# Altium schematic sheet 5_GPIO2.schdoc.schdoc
size 426 x 302 mm; Symbol: Sheet_A3_Whycan; Device: Sheet_A3; @Project Name: Avaota A1; REV: 1.0; Company: YuzukiHD; Draw By: GloomyGhost; @Update Date: 2024-02-28; @Page No: 7; @Page Count: 13
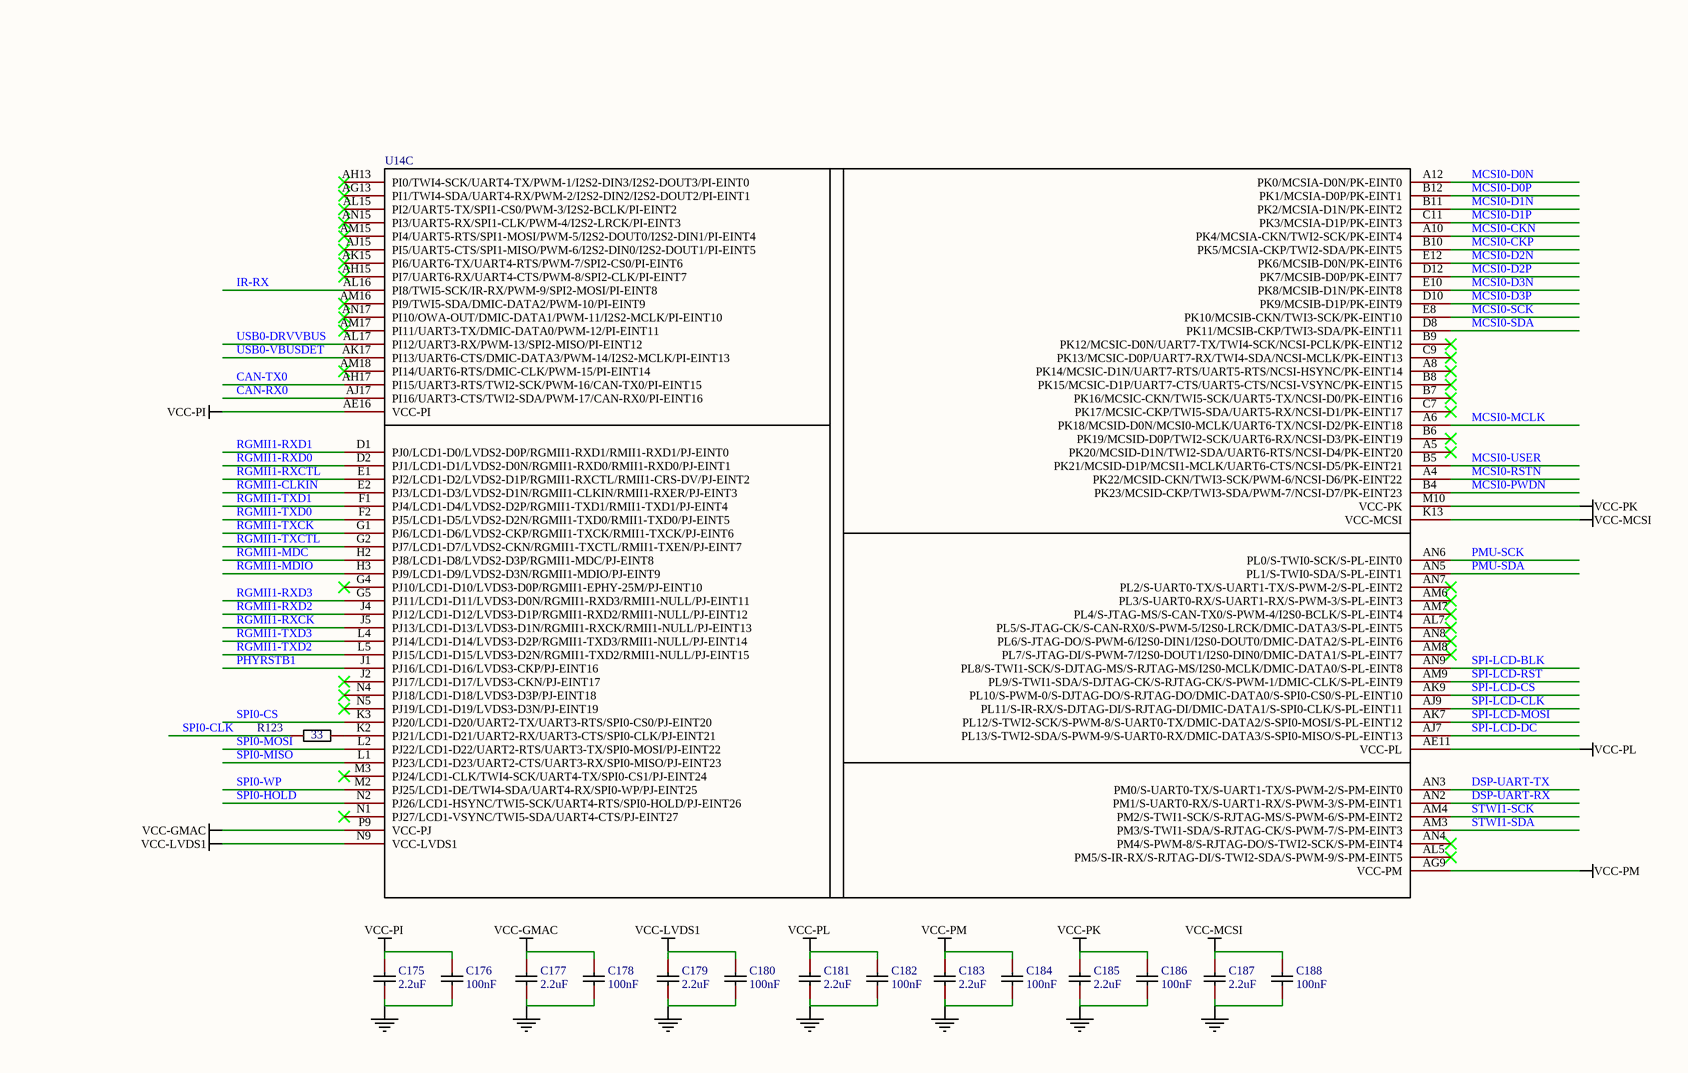
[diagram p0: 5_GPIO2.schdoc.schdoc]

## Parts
C175  2.2uF  [c0201 nsk]
C176  100nF  [c0201 nsk]
C177  2.2uF  [c0201 nsk]
C178  100nF  [c0201 nsk]
C179  2.2uF  [c0201 nsk]
C180  100nF  [c0201 nsk]
C181  2.2uF  [c0201 nsk]
C182  100nF  [c0201 nsk]
C183  2.2uF  [c0201 nsk]
C184  100nF  [c0201 nsk]
C185  2.2uF  [c0201 nsk]
C186  100nF  [c0201 nsk]
C187  2.2uF  [c0201 nsk]
C188  100nF  [c0201 nsk]
R123  33  [r0201 nsk]
U14  T527  [T527-BGA664]  (value not drawn)  (part C of 8)

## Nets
NetC175_1: C175.1 C176.1 C177.1 C178.1 C179.1 C180.1 C181.1 C182.1 C183.1 C184.1 C185.1 C186.1 C187.1 C188.1
VCC-GMAC: C177.2 C178.2 U14.P9(VCC-PJ)
VCC-LVDS1: C179.2 C180.2 U14.N9(VCC-LVDS1)
VCC-MCSI: C187.2 C188.2 U14.K13(VCC-MCSI)
VCC-PI: C175.2 C176.2 U14.AE16(VCC-PI)
VCC-PK: C185.2 C186.2 U14.M10(VCC-PK)
VCC-PL: C181.2 C182.2 U14.AE11(VCC-PL)
VCC-PM: C183.2 C184.2 U14.AG9(VCC-PM)
CAN-RX0: U14.AJ17(PI16/UART3-CTS/TWI2-SDA/PWM-17/CAN-RX0/PI-EINT16)
CAN-TX0: U14.AH17(PI15/UART3-RTS/TWI2-SCK/PWM-16/CAN-TX0/PI-EINT15)
DSP-UART-RX: U14.AN2(PM1/S-UART0-RX/S-UART1-RX/S-PWM-3/S-PM-EINT1)
DSP-UART-TX: U14.AN3(PM0/S-UART0-TX/S-UART1-TX/S-PWM-2/S-PM-EINT0)
IR-RX: U14.AL16(PI8/TWI5-SCK/IR-RX/PWM-9/SPI2-MOSI/PI-EINT8)
MCSI0-CKN: U14.A10(PK4/MCSIA-CKN/TWI2-SCK/PK-EINT4)
MCSI0-CKP: U14.B10(PK5/MCSIA-CKP/TWI2-SDA/PK-EINT5)
MCSI0-D0N: U14.A12(PK0/MCSIA-D0N/PK-EINT0)
MCSI0-D0P: U14.B12(PK1/MCSIA-D0P/PK-EINT1)
MCSI0-D1N: U14.B11(PK2/MCSIA-D1N/PK-EINT2)
MCSI0-D1P: U14.C11(PK3/MCSIA-D1P/PK-EINT3)
MCSI0-D2N: U14.E12(PK6/MCSIB-D0N/PK-EINT6)
MCSI0-D2P: U14.D12(PK7/MCSIB-D0P/PK-EINT7)
MCSI0-D3N: U14.E10(PK8/MCSIB-D1N/PK-EINT8)
MCSI0-D3P: U14.D10(PK9/MCSIB-D1P/PK-EINT9)
MCSI0-MCLK: U14.A6(PK18/MCSID-D0N/MCSI0-MCLK/UART6-TX/NCSI-D2/PK-EINT18)
MCSI0-PWDN: U14.B4(PK23/MCSID-CKP/TWI3-SDA/PWM-7/NCSI-D7/PK-EINT23)
MCSI0-RSTN: U14.A4(PK22/MCSID-CKN/TWI3-SCK/PWM-6/NCSI-D6/PK-EINT22)
MCSI0-SCK: U14.E8(PK10/MCSIB-CKN/TWI3-SCK/PK-EINT10)
MCSI0-SDA: U14.D8(PK11/MCSIB-CKP/TWI3-SDA/PK-EINT11)
MCSI0-USER: U14.B5(PK21/MCSID-D1P/MCSI1-MCLK/UART6-CTS/NCSI-D5/PK-EINT21)
PHYRSTB1: U14.J1(PJ16/LCD1-D16/LVDS3-CKP/PJ-EINT16)
PMU-SCK: U14.AN6(PL0/S-TWI0-SCK/S-PL-EINT0)
PMU-SDA: U14.AN5(PL1/S-TWI0-SDA/S-PL-EINT1)
RGMII1-CLKIN: U14.E2(PJ3/LCD1-D3/LVDS2-D1N/RGMII1-CLKIN/RMII1-RXER/PJ-EINT3)
RGMII1-MDC: U14.H2(PJ8/LCD1-D8/LVDS2-D3P/RGMII1-MDC/PJ-EINT8)
RGMII1-MDIO: U14.H3(PJ9/LCD1-D9/LVDS2-D3N/RGMII1-MDIO/PJ-EINT9)
RGMII1-RXCK: U14.J5(PJ13/LCD1-D13/LVDS3-D1N/RGMII1-RXCK/RMII1-NULL/PJ-EINT13)
RGMII1-RXCTL: U14.E1(PJ2/LCD1-D2/LVDS2-D1P/RGMII1-RXCTL/RMII1-CRS-DV/PJ-EINT2)
RGMII1-RXD0: U14.D2(PJ1/LCD1-D1/LVDS2-D0N/RGMII1-RXD0/RMII1-RXD0/PJ-EINT1)
RGMII1-RXD1: U14.D1(PJ0/LCD1-D0/LVDS2-D0P/RGMII1-RXD1/RMII1-RXD1/PJ-EINT0)
RGMII1-RXD2: U14.J4(PJ12/LCD1-D12/LVDS3-D1P/RGMII1-RXD2/RMII1-NULL/PJ-EINT12)
RGMII1-RXD3: U14.G5(PJ11/LCD1-D11/LVDS3-D0N/RGMII1-RXD3/RMII1-NULL/PJ-EINT11)
RGMII1-TXCK: U14.G1(PJ6/LCD1-D6/LVDS2-CKP/RGMII1-TXCK/RMII1-TXCK/PJ-EINT6)
RGMII1-TXCTL: U14.G2(PJ7/LCD1-D7/LVDS2-CKN/RGMII1-TXCTL/RMII1-TXEN/PJ-EINT7)
RGMII1-TXD0: U14.F2(PJ5/LCD1-D5/LVDS2-D2N/RGMII1-TXD0/RMII1-TXD0/PJ-EINT5)
RGMII1-TXD1: U14.F1(PJ4/LCD1-D4/LVDS2-D2P/RGMII1-TXD1/RMII1-TXD1/PJ-EINT4)
RGMII1-TXD2: U14.L5(PJ15/LCD1-D15/LVDS3-D2N/RGMII1-TXD2/RMII1-NULL/PJ-EINT15)
RGMII1-TXD3: U14.L4(PJ14/LCD1-D14/LVDS3-D2P/RGMII1-TXD3/RMII1-NULL/PJ-EINT14)
SPI0-CLK: R123.1
SPI0-CS: U14.K3(PJ20/LCD1-D20/UART2-TX/UART3-RTS/SPI0-CS0/PJ-EINT20)
SPI0-HOLD: U14.N2(PJ26/LCD1-HSYNC/TWI5-SCK/UART4-RTS/SPI0-HOLD/PJ-EINT26)
SPI0-MISO: U14.L1(PJ23/LCD1-D23/UART2-CTS/UART3-RX/SPI0-MISO/PJ-EINT23)
SPI0-MOSI: U14.L2(PJ22/LCD1-D22/UART2-RTS/UART3-TX/SPI0-MOSI/PJ-EINT22)
SPI0-WP: U14.M2(PJ25/LCD1-DE/TWI4-SDA/UART4-RX/SPI0-WP/PJ-EINT25)
SPI-LCD-BLK: U14.AN9(PL8/S-TWI1-SCK/S-DJTAG-MS/S-RJTAG-MS/I2S0-MCLK/DMIC-DATA0/S-PL-EINT8)
SPI-LCD-CLK: U14.AJ9(PL11/S-IR-RX/S-DJTAG-DI/S-RJTAG-DI/DMIC-DATA1/S-SPI0-CLK/S-PL-EINT11)
SPI-LCD-CS: U14.AK9(PL10/S-PWM-0/S-DJTAG-DO/S-RJTAG-DO/DMIC-DATA0/S-SPI0-CS0/S-PL-EINT10)
SPI-LCD-DC: U14.AJ7(PL13/S-TWI2-SDA/S-PWM-9/S-UART0-RX/DMIC-DATA3/S-SPI0-MISO/S-PL-EINT13)
SPI-LCD-MOSI: U14.AK7(PL12/S-TWI2-SCK/S-PWM-8/S-UART0-TX/DMIC-DATA2/S-SPI0-MOSI/S-PL-EINT12)
SPI-LCD-RST: U14.AM9(PL9/S-TWI1-SDA/S-DJTAG-CK/S-RJTAG-CK/S-PWM-1/DMIC-CLK/S-PL-EINT9)
STWI1-SCK: U14.AM4(PM2/S-TWI1-SCK/S-RJTAG-MS/S-PWM-6/S-PM-EINT2)
STWI1-SDA: U14.AM3(PM3/S-TWI1-SDA/S-RJTAG-CK/S-PWM-7/S-PM-EINT3)
USB0-DRVVBUS: U14.AL17(PI12/UART3-RX/PWM-13/SPI2-MISO/PI-EINT12)
USB0-VBUSDET: U14.AK17(PI13/UART6-CTS/DMIC-DATA3/PWM-14/I2S2-MCLK/PI-EINT13)
NetR123_2: R123.2 U14.K2(PJ21/LCD1-D21/UART2-RX/UART3-CTS/SPI0-CLK/PJ-EINT21)

Not connected (* = marked no-connect by the designer): U14 A5(PK20/MCSID-D1N/TWI2-SDA/UART6-RTS/NCSI-D4/PK-EINT20)* A8(PK14/MCSIC-D1N/UART7-RTS/UART5-RTS/NCSI-HSYNC/PK-EINT14)* AG13(PI1/TWI4-SDA/UART4-RX/PWM-2/I2S2-DIN2/I2S2-DOUT2/PI-EINT1)* AH13(PI0/TWI4-SCK/UART4-TX/PWM-1/I2S2-DIN3/I2S2-DOUT3/PI-EINT0)* AH15(PI7/UART6-RX/UART4-CTS/PWM-8/SPI2-CLK/PI-EINT7)* AJ15(PI5/UART5-CTS/SPI1-MISO/PWM-6/I2S2-DIN0/I2S2-DOUT1/PI-EINT5)* AK15(PI6/UART6-TX/UART4-RTS/PWM-7/SPI2-CS0/PI-EINT6)* AL5(PM5/S-IR-RX/S-RJTAG-DI/S-TWI2-SDA/S-PWM-9/S-PM-EINT5)* AL7(PL5/S-JTAG-CK/S-CAN-RX0/S-PWM-5/I2S0-LRCK/DMIC-DATA3/S-PL-EINT5)* AL15(PI2/UART5-TX/SPI1-CS0/PWM-3/I2S2-BCLK/PI-EINT2)* AM6(PL3/S-UART0-RX/S-UART1-RX/S-PWM-3/S-PL-EINT3)* AM7(PL4/S-JTAG-MS/S-CAN-TX0/S-PWM-4/I2S0-BCLK/S-PL-EINT4)* AM8(PL7/S-JTAG-DI/S-PWM-7/I2S0-DOUT1/I2S0-DIN0/DMIC-DATA1/S-PL-EINT7)* AM15(PI4/UART5-RTS/SPI1-MOSI/PWM-5/I2S2-DOUT0/I2S2-DIN1/PI-EINT4)* AM16(PI9/TWI5-SDA/DMIC-DATA2/PWM-10/PI-EINT9)* AM17(PI11/UART3-TX/DMIC-DATA0/PWM-12/PI-EINT11)* AM18(PI14/UART6-RTS/DMIC-CLK/PWM-15/PI-EINT14)* AN4(PM4/S-PWM-8/S-RJTAG-DO/S-TWI2-SCK/S-PM-EINT4)* AN7(PL2/S-UART0-TX/S-UART1-TX/S-PWM-2/S-PL-EINT2)* AN8(PL6/S-JTAG-DO/S-PWM-6/I2S0-DIN1/I2S0-DOUT0/DMIC-DATA2/S-PL-EINT6)* AN15(PI3/UART5-RX/SPI1-CLK/PWM-4/I2S2-LRCK/PI-EINT3)* AN17(PI10/OWA-OUT/DMIC-DATA1/PWM-11/I2S2-MCLK/PI-EINT10)* B6(PK19/MCSID-D0P/TWI2-SCK/UART6-RX/NCSI-D3/PK-EINT19)* B7(PK16/MCSIC-CKN/TWI5-SCK/UART5-TX/NCSI-D0/PK-EINT16)* B8(PK15/MCSIC-D1P/UART7-CTS/UART5-CTS/NCSI-VSYNC/PK-EINT15)* B9(PK12/MCSIC-D0N/UART7-TX/TWI4-SCK/NCSI-PCLK/PK-EINT12)* C7(PK17/MCSIC-CKP/TWI5-SDA/UART5-RX/NCSI-D1/PK-EINT17)* C9(PK13/MCSIC-D0P/UART7-RX/TWI4-SDA/NCSI-MCLK/PK-EINT13)* G4(PJ10/LCD1-D10/LVDS3-D0P/RGMII1-EPHY-25M/PJ-EINT10)* J2(PJ17/LCD1-D17/LVDS3-CKN/PJ-EINT17)* M3(PJ24/LCD1-CLK/TWI4-SCK/UART4-TX/SPI0-CS1/PJ-EINT24)* N1(PJ27/LCD1-VSYNC/TWI5-SDA/UART4-CTS/PJ-EINT27)* N4(PJ18/LCD1-D18/LVDS3-D3P/PJ-EINT18)* N5(PJ19/LCD1-D19/LVDS3-D3N/PJ-EINT19)*

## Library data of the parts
C175-C188 = GRM033R61A104KE15D: Manufacturer: muRata(村田); Add into BOM: yes; Tolerance: ±10%; Voltage Rated: 10V; Temperature Coefficient: X5R; Description: 容值:100nF;精度:±10%;额定电压:10V;材质(温度系数):X5R;
R123 = Res_0201: Symbol: 电阻; Convert to PCB: yes
U14 = T527: Add into BOM: yes; SWAP_INFO: (S1+S2+S3+S4+S5+S6+S7+S8+S9); SPLIT_INST: TRUE; Description: Allwinner T527 SoC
